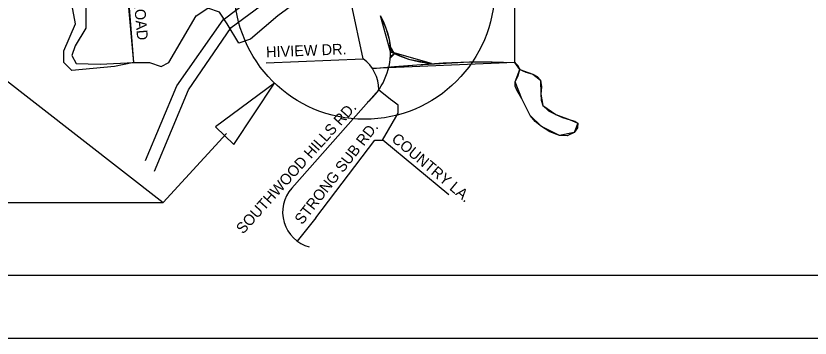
# Model space of a CAD drawing. Extents: x 5.01 to 9.58, y 0.27 to 3.39.
# Drawn here: x 7.24 to 8.037, y 0.321 to 0.644 of the extents above; entities that cross this region are included whole.
import ezdxf

# ---------------------------------------------------------------- set-up
doc = ezdxf.new("R2010")
doc.units = 0
for name, color, linetype in [('Level 7', 7, 'Continuous'), ('Level 9', 7, 'Continuous'), ('MO_001_NOSHOW', 7, 'Continuous'), ('MO_001_VIEW_99', 7, 'Continuous'), ('MO_001_VIEW_PV', 7, 'Continuous')]:
    doc.layers.add(name, color=color, linetype=linetype)

msp = doc.modelspace()

# ---------------------------------------------------------------- linework, layer by layer
at = {"layer": 'Level 7'}
for p, q in [((6.92435, 0.81688), (7.38772, 0.45685)), ((7.49925, 0.57629), (7.44, 0.53251)), ((7.45851, 0.51497), (7.49925, 0.57629)), ((7.38772, 0.45685), (7.45133, 0.52596)), ((7.45851, 0.51497), (7.44, 0.53251)), ((6.06398, 0.45685), (7.38772, 0.45685)), ((5.30436, 0.3838), (8.26663, 0.3838))]:
    msp.add_line(p, q, dxfattribs=at)
msp.add_lwpolyline([(7.49925, 0.57629), (7.44, 0.53251), (7.45851, 0.51497)], close=True, dxfattribs=at)
msp.add_circle((7.58964, 0.6707), 0.13045, dxfattribs=at)
at = {"layer": 'Level 9'}
msp.add_lwpolyline([(7.32131, 0.74131), (7.30837, 0.72972), (7.29394, 0.71281), (7.28858, 0.6996), (7.30012, 0.68228), (7.31002, 0.65547), (7.31002, 0.63155), (7.2993, 0.61381), (7.296, 0.60432), (7.30054, 0.59607), (7.32446, 0.59565), (7.35834, 0.59707), (7.3486, 0.70427), (7.33477, 0.73797)], dxfattribs=at)
at = {"layer": 'MO_001_NOSHOW'}
for points in [[(7.60569, 0.64396), (7.61107, 0.63152), (7.6143, 0.62059), (7.61582, 0.60782)], [(7.61542, 0.61361), (7.61708, 0.60926), (7.61986, 0.60589)], [(7.61554, 0.60182), (7.61681, 0.60433), (7.61986, 0.60589)], [(7.61582, 0.60782), (7.63378, 0.6006), (7.65679, 0.59607)], [(7.59759, 0.59104), (7.64206, 0.59497), (7.69497, 0.59791), (7.74035, 0.59707)], [(7.74035, 0.59707), (7.74552, 0.59017), (7.75837, 0.58555), (7.76609, 0.57938), (7.7666, 0.56549), (7.76866, 0.55418), (7.78151, 0.54492), (7.79591, 0.53979), (7.80361, 0.53618), (7.80002, 0.52693), (7.78511, 0.52384), (7.76711, 0.5331), (7.7558, 0.5439), (7.74758, 0.56087), (7.74089, 0.57783), (7.74552, 0.59017), (7.74035, 0.59707)]]:
    msp.add_lwpolyline(points, close=True, dxfattribs=at)
at = {"layer": 'MO_001_VIEW_99'}
msp.add_line((5.01404, 0.3206), (9.57964, 0.3206), dxfattribs=at)
at = {"layer": 'MO_001_VIEW_PV'}
for p, q in [((7.49091, 0.59701), (7.58832, 0.60092)), ((7.37394, 0.59701), (7.35829, 0.59701)), ((7.51657, 0.47105), (7.60397, 0.56976)), ((7.60397, 0.56976), (7.61687, 0.55947)), ((7.67411, 0.46453), (7.60788, 0.51917)), ((7.54077, 0.44134), (7.52222, 0.418))]:
    msp.add_line(p, q, dxfattribs=at)
for points in [[(7.74035, 0.59707), (7.74035, 0.71012), (7.75593, 0.78028), (7.75593, 0.80758), (7.74814, 0.83096), (7.72866, 0.85045), (7.72476, 0.85434)], [(7.35834, 0.59707), (7.35055, 0.69452), (7.34665, 0.71403)], [(7.37002, 0.49881), (7.4012, 0.57368), (7.448, 0.63996), (7.49866, 0.67894), (7.55558, 0.71231)], [(7.35834, 0.59707), (7.33884, 0.59318), (7.29596, 0.58928), (7.28817, 0.59707), (7.28817, 0.60876), (7.29986, 0.63606), (7.29596, 0.65555), (7.28817, 0.67504), (7.26089, 0.70232)], [(7.37882, 0.48797), (7.41291, 0.56979), (7.45579, 0.63217), (7.50256, 0.66725), (7.56143, 0.70257)], [(7.58832, 0.60097), (7.57662, 0.65555), (7.56883, 0.66334), (7.55714, 0.67113), (7.53376, 0.66725), (7.50256, 0.64386), (7.47527, 0.62048), (7.46358, 0.61656), (7.45189, 0.63606), (7.4441, 0.64775), (7.4324, 0.65165)], [(7.37393, 0.59707), (7.38562, 0.59318), (7.39341, 0.59707), (7.42071, 0.64386), (7.4324, 0.65165)], [(7.60569, 0.64396), (7.60857, 0.63783), (7.61107, 0.63152), (7.61287, 0.6261), (7.6143, 0.62059), (7.61535, 0.61423), (7.61582, 0.60782)], [(7.61542, 0.61361), (7.61607, 0.61137), (7.61708, 0.60926), (7.61833, 0.60747), (7.61986, 0.60589)], [(7.61554, 0.60182), (7.61602, 0.60316), (7.61681, 0.60433), (7.61821, 0.60535), (7.61986, 0.60589)], [(7.61582, 0.60782), (7.62465, 0.60383), (7.63378, 0.6006), (7.64518, 0.59775), (7.65679, 0.59607)], [(7.59759, 0.59104), (7.61981, 0.59315), (7.64206, 0.59497), (7.6685, 0.59682), (7.69497, 0.59791), (7.71767, 0.5979), (7.74035, 0.59707)], [(7.74548, 0.5902), (7.7455, 0.59018), (7.74552, 0.59017), (7.75159, 0.58753), (7.75837, 0.58555), (7.76291, 0.583), (7.76609, 0.57938), (7.7672, 0.57284), (7.7666, 0.56549), (7.76683, 0.55948), (7.76866, 0.55418), (7.77424, 0.54874), (7.78151, 0.54492), (7.78837, 0.54211), (7.79591, 0.53979), (7.80052, 0.53846), (7.80361, 0.53618), (7.80331, 0.53163), (7.80002, 0.52693), (7.7929, 0.52348), (7.78511, 0.52384), (7.77566, 0.52748), (7.76711, 0.5331), (7.76092, 0.53813), (7.7558, 0.5439), (7.75164, 0.55205), (7.74758, 0.56087), (7.74252, 0.56934), (7.74091, 0.57357), (7.74089, 0.57783), (7.74381, 0.58405), (7.74552, 0.59017), (7.74364, 0.59395), (7.74035, 0.59707)], [(7.60782, 0.51911), (7.6234, 0.54641), (7.6234, 0.5542), (7.6168, 0.55948)], [(7.54072, 0.44129), (7.60001, 0.51911), (7.60782, 0.51911)]]:
    msp.add_lwpolyline(points, dxfattribs=at)
for centre, radius, start, end in [((7.54909, 0.60782), 0.06672, 310.82863, 0.00001), ((7.56494, 0.56979), 0.03896, 0, 53.12975), ((7.54372, 0.44709), 0.03623, 138.49452, 254.62585)]:
    msp.add_arc(centre, radius, start, end, dxfattribs=at)

# ---------------------------------------------------------------- texts
for s, height, rotation, p in [('ROAD', 0.01087, 275, (7.35806, 0.66093)), ('HIVIEW DR.', 0.01087, 2.2, (7.49107, 0.6023)), ('SOUTHWOOD HILLS RD.', 0.0108704, 48, (7.46781, 0.42437)), ('STRONG SUB RD.', 0.0108704, 52, (7.52711, 0.43376)), ('COUNTRY LA.', 0.0108704, 320, (7.61589, 0.51897))]:
    msp.add_text(s, height=height, rotation=rotation, dxfattribs=at).set_placement(p)

doc.saveas('drawing.dxf')
